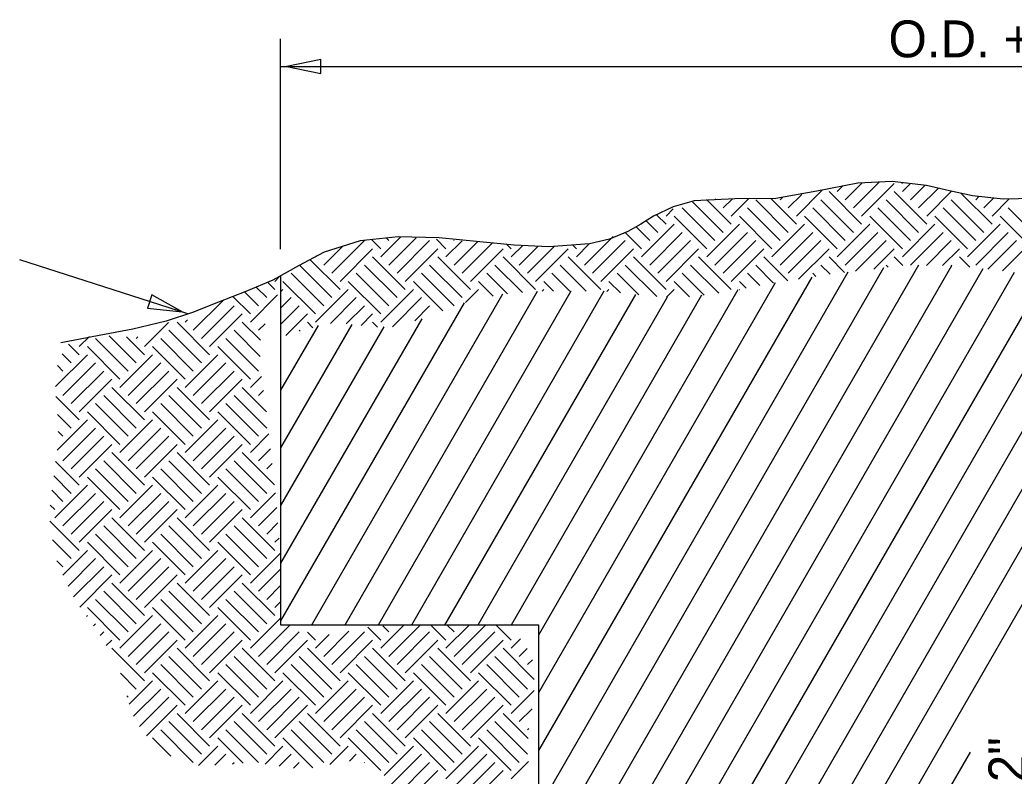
# Model space of a CAD drawing. Extents: x -439.1 to -407.9, y -458.1 to -436.2.
# Drawn here: x -425.749 to -421.705, y -441.707 to -438.633 of the extents above; entities that cross this region are included whole.
import ezdxf

# ---------------------------------------------------------------- set-up
doc = ezdxf.new("R2010")
doc.units = 0
doc.layers.add('Level 4', color=7, linetype='Continuous')
doc.layers.add('Level 45', color=7, linetype='Continuous')

msp = doc.modelspace()

# ---------------------------------------------------------------- linework, layer by layer
at = {"layer": 'Level 4'}
for p, q in [((-424.6882, -439.5658), (-424.6882, -438.7104)), ((-424.6882, -438.8229), (-418.4367, -438.8229)), ((-422.3917, -439.3647), (-422.3229, -439.2959)), ((-422.3585, -439.3978), (-422.2537, -439.293)), ((-422.3254, -439.431), (-422.1928, -439.2984)), ((-422.1596, -439.2984), (-422.1628, -439.2952)), ((-422.1596, -439.3315), (-422.1274, -439.2993)), ((-422.5905, -439.431), (-422.484, -439.3244)), ((-422.3254, -439.4641), (-422.4579, -439.3315)), ((-422.4248, -439.3315), (-422.4001, -439.3069)), ((-422.0602, -439.4641), (-422.1928, -439.3315)), ((-422.1265, -439.3647), (-422.068, -439.3062)), ((-422.0933, -439.3978), (-422.013, -439.3175)), ((-422.0602, -439.431), (-421.9592, -439.33)), ((-421.795, -439.4641), (-421.9203, -439.3388)), ((-422.8888, -439.4972), (-423.0138, -439.3723)), ((-422.8557, -439.4641), (-422.9559, -439.3639)), ((-422.922, -439.3647), (-422.9178, -439.3604)), ((-422.8888, -439.3978), (-422.8511, -439.3601)), ((-422.8557, -439.431), (-422.7858, -439.3611)), ((-422.6237, -439.4972), (-422.7562, -439.3647)), ((-422.5905, -439.4641), (-422.695, -439.3596)), ((-422.6568, -439.3647), (-422.6474, -439.3553)), ((-422.6237, -439.3978), (-422.5686, -439.3427)), ((-422.3585, -439.4972), (-422.4911, -439.3647)), ((-422.0933, -439.4972), (-422.2259, -439.3647)), ((-421.8282, -439.4972), (-421.9608, -439.3647)), ((-421.8613, -439.3647), (-421.8481, -439.3515)), ((-421.8282, -439.3978), (-421.7885, -439.3581)), ((-421.795, -439.431), (-421.7259, -439.3618)), ((-423.1209, -439.431), (-423.0912, -439.4013)), ((-422.922, -439.5304), (-423.0546, -439.3978)), ((-422.6568, -439.5304), (-422.7894, -439.3978)), ((-422.3917, -439.5304), (-422.5242, -439.3978)), ((-422.1265, -439.5304), (-422.2591, -439.3978)), ((-421.8613, -439.5304), (-421.9939, -439.3978)), ((-421.5962, -439.5304), (-421.7287, -439.3978)), ((-423.154, -439.4972), (-423.2017, -439.4496)), ((-423.1209, -439.4641), (-423.1584, -439.4265)), ((-422.9551, -439.5635), (-423.0877, -439.431)), ((-422.69, -439.5635), (-422.8225, -439.431)), ((-422.4248, -439.5635), (-422.5574, -439.431)), ((-422.1596, -439.5635), (-422.2922, -439.431)), ((-421.8945, -439.5635), (-422.0271, -439.431)), ((-421.6293, -439.5635), (-421.7619, -439.431)), ((-423.2203, -439.5635), (-423.2865, -439.4974)), ((-423.1871, -439.5304), (-423.2426, -439.4749)), ((-423.2203, -439.5967), (-423.0877, -439.4641)), ((-423.1871, -439.6298), (-423.0546, -439.4972)), ((-422.9551, -439.5967), (-422.8225, -439.4641)), ((-422.922, -439.6298), (-422.7894, -439.4972)), ((-422.69, -439.5967), (-422.5574, -439.4641)), ((-422.6568, -439.6298), (-422.5242, -439.4972)), ((-422.4248, -439.5967), (-422.2922, -439.4641)), ((-422.3917, -439.6298), (-422.2591, -439.4972)), ((-422.1596, -439.5967), (-422.0271, -439.4641)), ((-422.1265, -439.6298), (-421.9939, -439.4972)), ((-421.8945, -439.5967), (-421.7619, -439.4641)), ((-421.8613, -439.6298), (-421.7287, -439.4972)), ((-424.4798, -439.663), (-424.3472, -439.5304)), ((-424.281, -439.5635), (-424.3182, -439.5263)), ((-424.281, -439.5967), (-424.1997, -439.5154)), ((-424.2478, -439.5304), (-424.2583, -439.5199)), ((-424.2478, -439.6298), (-424.1373, -439.5193)), ((-424.2147, -439.663), (-424.0821, -439.5304)), ((-424.0158, -439.5635), (-424.0549, -439.5245)), ((-424.0158, -439.5967), (-423.9501, -439.531)), ((-423.9826, -439.5304), (-423.9842, -439.5289)), ((-423.9826, -439.6298), (-423.8877, -439.5349)), ((-423.9495, -439.663), (-423.8259, -439.5394)), ((-423.4523, -439.6298), (-423.3357, -439.5132)), ((-423.4192, -439.663), (-423.2866, -439.5304)), ((-423.154, -439.663), (-423.0214, -439.5304)), ((-422.8888, -439.663), (-422.7562, -439.5304)), ((-422.6237, -439.663), (-422.4911, -439.5304)), ((-422.3506, -439.655), (-422.2259, -439.5304)), ((-422.0614, -439.631), (-421.9608, -439.5304)), ((-421.812, -439.6468), (-421.6956, -439.5304)), ((-424.513, -439.6298), (-424.4369, -439.5538)), ((-424.4467, -439.6961), (-424.3141, -439.5635)), ((-424.1815, -439.6961), (-424.0489, -439.5635)), ((-423.9164, -439.6961), (-423.7838, -439.5635)), ((-423.7506, -439.5635), (-423.7707, -439.5435)), ((-423.7506, -439.5967), (-423.7025, -439.5485)), ((-423.7175, -439.6298), (-423.6407, -439.5531)), ((-423.6843, -439.663), (-423.576, -439.5547)), ((-423.6512, -439.6961), (-423.5186, -439.5635)), ((-423.4855, -439.5635), (-423.4999, -439.5491)), ((-423.4855, -439.5967), (-423.433, -439.5442)), ((-423.386, -439.6961), (-423.2534, -439.5635)), ((-423.1209, -439.6961), (-422.9883, -439.5635)), ((-422.8557, -439.6961), (-422.7231, -439.5635)), ((-422.5814, -439.687), (-422.4579, -439.5635)), ((-422.2752, -439.646), (-422.1928, -439.5635)), ((-421.9962, -439.6321), (-421.9276, -439.5635)), ((-421.7524, -439.6535), (-421.6624, -439.5635)), ((-425.0651, -439.8279), (-425.7487, -439.6091)), ((-424.4467, -439.7293), (-424.5691, -439.6068)), ((-424.5461, -439.5967), (-424.5424, -439.593)), ((-424.1815, -439.7293), (-424.3141, -439.5967)), ((-423.9164, -439.7293), (-424.0489, -439.5967)), ((-423.6512, -439.7293), (-423.7838, -439.5967)), ((-420.8581, -439.5989), (-423.5795, -444.3124)), ((-423.386, -439.7293), (-423.5186, -439.5967)), ((-423.1209, -439.7293), (-423.2534, -439.5967)), ((-422.8557, -439.7293), (-422.9883, -439.5967)), ((-422.6258, -439.694), (-422.7231, -439.5967)), ((-422.3943, -439.6603), (-422.4579, -439.5967)), ((-422.1576, -439.6319), (-422.1928, -439.5967)), ((-421.8857, -439.6386), (-421.9276, -439.5967)), ((-424.513, -439.7956), (-424.6456, -439.663)), ((-424.4798, -439.7624), (-424.6114, -439.6308)), ((-424.2478, -439.7956), (-424.3804, -439.663)), ((-424.2147, -439.7624), (-424.3472, -439.6298)), ((-423.9826, -439.7956), (-424.1152, -439.663)), ((-423.9495, -439.7624), (-424.0821, -439.6298)), ((-423.7661, -439.747), (-423.8501, -439.663)), ((-423.7046, -439.7421), (-423.8169, -439.6298)), ((-422.0942, -439.6304), (-423.6394, -442.3068)), ((-421.9602, -439.6327), (-423.6394, -442.5412)), ((-422.2358, -439.6413), (-423.6394, -442.0724)), ((-421.8318, -439.6446), (-423.6394, -442.7755)), ((-422.3812, -439.6587), (-423.6394, -441.838)), ((-421.7051, -439.6596), (-423.6394, -443.0099)), ((-423.5125, -439.7354), (-423.5849, -439.663)), ((-423.4462, -439.7354), (-423.5517, -439.6298)), ((-423.2319, -439.7508), (-423.3197, -439.663)), ((-423.1586, -439.7578), (-423.2866, -439.6298)), ((-422.9659, -439.7516), (-423.0546, -439.663)), ((-422.9067, -439.7446), (-423.0214, -439.6298)), ((-422.7396, -439.7128), (-422.7894, -439.663)), ((-422.6831, -439.703), (-422.7562, -439.6298)), ((-422.5113, -439.6759), (-422.5242, -439.663)), ((-422.4535, -439.6674), (-422.4911, -439.6298)), ((-422.2168, -439.639), (-422.2259, -439.6298)), ((-421.9578, -439.6328), (-421.9608, -439.6298)), ((-424.7118, -439.7293), (-424.7407, -439.7005)), ((-424.7118, -439.6961), (-424.6938, -439.678)), ((-424.6884, -439.6753), (-424.6884, -441.0928)), ((-424.5461, -439.8287), (-424.6787, -439.6961)), ((-424.281, -439.8287), (-424.4135, -439.6961)), ((-424.0289, -439.8156), (-424.1484, -439.6961)), ((-423.8232, -439.7561), (-423.8832, -439.6961)), ((-421.5804, -439.6779), (-423.6394, -443.2443)), ((-422.5279, -439.6785), (-423.6394, -441.6037)), ((-421.0426, -439.684), (-423.6394, -444.1818)), ((-421.4551, -439.6953), (-423.6394, -443.4787)), ((-422.6768, -439.702), (-423.6394, -441.3693)), ((-421.3238, -439.7023), (-423.6394, -443.713)), ((-423.5788, -439.7354), (-423.618, -439.6961)), ((-423.3066, -439.7424), (-423.3529, -439.6961)), ((-423.0251, -439.7587), (-423.0877, -439.6961)), ((-422.7948, -439.7238), (-422.8225, -439.6961)), ((-424.7781, -439.7956), (-424.835, -439.7387)), ((-424.745, -439.7624), (-424.7869, -439.7205)), ((-424.6882, -439.7388), (-424.6787, -439.7293)), ((-424.5461, -439.8619), (-424.4135, -439.7293)), ((-423.6444, -439.7374), (-424.4272, -441.0932)), ((-423.5079, -439.7354), (-424.2919, -441.0932)), ((-424.281, -439.8619), (-424.1484, -439.7293)), ((-423.3731, -439.7361), (-424.1566, -441.0932)), ((-423.936, -439.7821), (-423.8832, -439.7293)), ((-421.1918, -439.708), (-423.6394, -443.9474)), ((-422.8286, -439.7306), (-423.6394, -441.1349)), ((-423.6246, -439.7358), (-423.618, -439.7293)), ((-423.3609, -439.7373), (-423.3529, -439.7293)), ((-423.1188, -439.7604), (-423.0877, -439.7293)), ((-422.8227, -439.7294), (-422.8225, -439.7293)), ((-425.0433, -439.895), (-424.9204, -439.772)), ((-424.8113, -439.8287), (-424.8828, -439.7572)), ((-424.8113, -439.8619), (-424.7006, -439.7512)), ((-424.6882, -439.8051), (-424.6456, -439.7624)), ((-423.9416, -439.7834), (-424.6882, -441.0766)), ((-423.7862, -439.7486), (-424.5625, -441.0932)), ((-424.4856, -439.8676), (-424.3804, -439.7624)), ((-424.2337, -439.8809), (-424.1152, -439.7624)), ((-423.2453, -439.7492), (-424.0212, -441.0932)), ((-423.1165, -439.7604), (-423.8859, -441.0932)), ((-422.9768, -439.7529), (-423.7506, -441.0932)), ((-425.0102, -439.9281), (-424.8776, -439.7956)), ((-424.6882, -439.8714), (-424.6124, -439.7956)), ((-424.4211, -439.8694), (-424.3472, -439.7956)), ((-424.1431, -439.8566), (-424.0821, -439.7956)), ((-425.2422, -439.9613), (-425.1441, -439.8632)), ((-424.977, -439.9944), (-425.1096, -439.8619)), ((-425.0764, -439.8619), (-425.0669, -439.8523)), ((-424.977, -439.9613), (-424.8444, -439.8287)), ((-424.7707, -439.9356), (-424.8444, -439.8619)), ((-424.1144, -439.8483), (-424.6882, -440.8422)), ((-424.6666, -439.916), (-424.5793, -439.8287)), ((-424.5566, -439.8845), (-424.5793, -439.8619)), ((-424.3611, -439.8757), (-424.3141, -439.8287)), ((-424.2941, -439.8818), (-424.3141, -439.8619)), ((-425.0102, -440.0276), (-425.1427, -439.895)), ((-424.7712, -440.0014), (-424.8776, -439.895)), ((-424.7781, -439.895), (-424.7515, -439.8684)), ((-424.3986, -439.8717), (-424.6882, -440.3734)), ((-424.5362, -439.8757), (-424.6882, -440.1391)), ((-424.2689, -439.8816), (-424.6882, -440.6078)), ((-424.6092, -439.8982), (-424.6124, -439.895)), ((-425.5073, -439.9613), (-425.4658, -439.9198)), ((-425.3085, -440.0607), (-425.4411, -439.9281)), ((-425.2753, -440.0276), (-425.3851, -439.9178)), ((-425.2422, -439.9944), (-425.315, -439.9216)), ((-425.2753, -439.9281), (-425.2688, -439.9216)), ((-425.0433, -440.0607), (-425.1759, -439.9281)), ((-424.7781, -440.0607), (-424.9107, -439.9281)), ((-425.5073, -439.9944), (-425.5509, -439.9509)), ((-425.3416, -440.0939), (-425.4742, -439.9613)), ((-425.0764, -440.0939), (-425.209, -439.9613)), ((-424.8113, -440.0939), (-424.9439, -439.9613)), ((-425.6038, -440.124), (-425.4742, -439.9944)), ((-425.5405, -440.0276), (-425.5771, -439.991)), ((-425.3416, -440.127), (-425.209, -439.9944)), ((-425.0764, -440.127), (-424.9439, -439.9944)), ((-425.5736, -440.0607), (-425.5959, -440.0384)), ((-425.5736, -440.1602), (-425.4411, -440.0276)), ((-425.5405, -440.1933), (-425.4079, -440.0607)), ((-425.3085, -440.1602), (-425.1759, -440.0276)), ((-425.2753, -440.1933), (-425.1427, -440.0607)), ((-425.0433, -440.1602), (-424.9107, -440.0276)), ((-425.0102, -440.1933), (-424.8776, -440.0607)), ((-425.5073, -440.2265), (-425.3748, -440.0939)), ((-425.2422, -440.2265), (-425.1096, -440.0939)), ((-424.977, -440.2265), (-424.8444, -440.0939)), ((-424.8113, -440.127), (-424.7667, -440.0825)), ((-425.2422, -440.2596), (-425.3748, -440.127)), ((-424.977, -440.2596), (-425.1096, -440.127)), ((-424.7453, -440.2261), (-424.8444, -440.127)), ((-424.7781, -440.1602), (-424.7575, -440.1395)), ((-425.5073, -440.2596), (-425.6022, -440.1647)), ((-425.2753, -440.2927), (-425.4079, -440.1602)), ((-425.0102, -440.2927), (-425.1427, -440.1602)), ((-424.745, -440.2927), (-424.8776, -440.1602)), ((-425.3416, -440.359), (-425.4742, -440.2265)), ((-425.3085, -440.3259), (-425.4411, -440.1933)), ((-425.0764, -440.359), (-425.209, -440.2265)), ((-425.0433, -440.3259), (-425.1759, -440.1933)), ((-424.8113, -440.359), (-424.9439, -440.2265)), ((-424.7781, -440.3259), (-424.9107, -440.1933)), ((-425.5976, -440.383), (-425.4742, -440.2596)), ((-425.5405, -440.2927), (-425.5964, -440.2368)), ((-425.3416, -440.3922), (-425.209, -440.2596)), ((-425.0764, -440.3922), (-424.9439, -440.2596)), ((-425.5736, -440.3259), (-425.5935, -440.306)), ((-425.5736, -440.4253), (-425.4411, -440.2927)), ((-425.3085, -440.4253), (-425.1759, -440.2927)), ((-425.0433, -440.4253), (-424.9107, -440.2927)), ((-425.5405, -440.4585), (-425.4079, -440.3259)), ((-425.2753, -440.4585), (-425.1427, -440.3259)), ((-425.0102, -440.4585), (-424.8776, -440.3259)), ((-424.8113, -440.3922), (-424.7356, -440.3165)), ((-425.5073, -440.4916), (-425.3748, -440.359)), ((-425.2422, -440.4916), (-425.1096, -440.359)), ((-424.977, -440.4916), (-424.8444, -440.359)), ((-424.7781, -440.4253), (-424.7291, -440.3763)), ((-425.5073, -440.5248), (-425.6033, -440.4288)), ((-425.2753, -440.5579), (-425.4079, -440.4253)), ((-425.2422, -440.5248), (-425.3748, -440.3922)), ((-425.0102, -440.5579), (-425.1427, -440.4253)), ((-424.977, -440.5248), (-425.1096, -440.3922)), ((-424.745, -440.5579), (-424.8776, -440.4253)), ((-424.7132, -440.5234), (-424.8444, -440.3922)), ((-425.3085, -440.5911), (-425.4411, -440.4585)), ((-425.0433, -440.5911), (-425.1759, -440.4585)), ((-424.7781, -440.5911), (-424.9107, -440.4585)), ((-424.745, -440.4585), (-424.7226, -440.4361)), ((-425.5405, -440.5579), (-425.6112, -440.4872)), ((-425.3416, -440.6242), (-425.4742, -440.4916)), ((-425.0764, -440.6242), (-425.209, -440.4916)), ((-424.8113, -440.6242), (-424.9439, -440.4916)), ((-425.5736, -440.5911), (-425.6192, -440.5455)), ((-425.6068, -440.6573), (-425.4742, -440.5248)), ((-425.3416, -440.6573), (-425.209, -440.5248)), ((-425.0764, -440.6573), (-424.9439, -440.5248)), ((-425.5736, -440.6905), (-425.4411, -440.5579)), ((-425.5405, -440.7236), (-425.4079, -440.5911)), ((-425.3085, -440.6905), (-425.1759, -440.5579)), ((-425.2753, -440.7236), (-425.1427, -440.5911)), ((-425.0433, -440.6905), (-424.9107, -440.5579)), ((-425.0102, -440.7236), (-424.8776, -440.5911)), ((-424.8113, -440.6573), (-424.7097, -440.5557)), ((-425.6068, -440.6242), (-425.6254, -440.6056)), ((-425.5073, -440.7568), (-425.3748, -440.6242)), ((-425.2422, -440.7568), (-425.1096, -440.6242)), ((-424.977, -440.7568), (-424.8444, -440.6242)), ((-424.7781, -440.6905), (-424.7035, -440.6158)), ((-425.5073, -440.7899), (-425.6267, -440.6706)), ((-425.2422, -440.7899), (-425.3748, -440.6573)), ((-424.977, -440.7899), (-425.1096, -440.6573)), ((-424.7118, -440.7899), (-424.8444, -440.6573)), ((-425.2753, -440.8231), (-425.4079, -440.6905)), ((-425.0102, -440.8231), (-425.1427, -440.6905)), ((-424.745, -440.8231), (-424.8776, -440.6905)), ((-424.745, -440.7236), (-424.6991, -440.6778)), ((-425.5405, -440.8231), (-425.6162, -440.7474)), ((-425.3085, -440.8562), (-425.4411, -440.7236)), ((-425.0433, -440.8562), (-425.1759, -440.7236)), ((-424.7781, -440.8562), (-424.9107, -440.7236)), ((-424.7118, -440.7568), (-424.6947, -440.7397)), ((-425.5746, -440.8903), (-425.4742, -440.7899)), ((-425.3416, -440.8894), (-425.4742, -440.7568)), ((-425.3416, -440.9225), (-425.209, -440.7899)), ((-425.0764, -440.8894), (-425.209, -440.7568)), ((-425.0764, -440.9225), (-424.9439, -440.7899)), ((-424.8113, -440.8894), (-424.9439, -440.7568)), ((-425.5736, -440.8562), (-425.5982, -440.8316)), ((-425.5528, -440.9348), (-425.4411, -440.8231)), ((-425.3085, -440.9557), (-425.1759, -440.8231)), ((-425.0433, -440.9557), (-424.9107, -440.8231)), ((-424.8113, -440.9225), (-424.6908, -440.802)), ((-425.531, -440.9793), (-425.4079, -440.8562)), ((-425.2753, -440.9888), (-425.1427, -440.8562)), ((-425.0102, -440.9888), (-424.8776, -440.8562)), ((-424.7781, -440.9557), (-424.6902, -440.8677)), ((-425.5054, -441.02), (-425.3748, -440.8894)), ((-425.2422, -441.0219), (-425.1096, -440.8894)), ((-424.977, -441.0219), (-424.8444, -440.8894)), ((-425.2753, -441.0882), (-425.4079, -440.9557)), ((-425.2422, -441.0551), (-425.3748, -440.9225)), ((-425.0102, -441.0882), (-425.1427, -440.9557)), ((-424.977, -441.0551), (-425.1096, -440.9225)), ((-424.745, -441.0882), (-424.8776, -440.9557)), ((-424.7118, -441.0551), (-424.8444, -440.9225)), ((-424.745, -440.9888), (-424.6896, -440.9334)), ((-425.3085, -441.1214), (-425.4411, -440.9888)), ((-425.0433, -441.1214), (-425.1759, -440.9888)), ((-424.7781, -441.1214), (-424.9107, -440.9888)), ((-425.3416, -441.1545), (-425.4742, -441.0219)), ((-425.0764, -441.1545), (-425.209, -441.0219)), ((-424.8113, -441.1545), (-424.9439, -441.0219)), ((-424.7118, -441.0219), (-424.6891, -440.9992)), ((-425.4779, -441.0588), (-425.4742, -441.0551)), ((-425.3416, -441.1877), (-425.209, -441.0551)), ((-425.0764, -441.1877), (-424.9439, -441.0551)), ((-424.8113, -441.1877), (-424.6885, -441.0649)), ((-425.4498, -441.0969), (-425.4411, -441.0882)), ((-425.3085, -441.2208), (-425.1759, -441.0882)), ((-425.0433, -441.2208), (-424.9107, -441.0882)), ((-424.7781, -441.2208), (-424.6505, -441.0932)), ((-424.6884, -441.0928), (-423.6397, -441.0928)), ((-424.513, -441.2208), (-424.4105, -441.1184)), ((-424.281, -441.1545), (-424.3333, -441.1022)), ((-424.281, -441.1877), (-424.1865, -441.0932)), ((-424.2478, -441.1214), (-424.2723, -441.0969)), ((-424.2478, -441.2208), (-424.1202, -441.0932)), ((-424.0158, -441.1545), (-424.0771, -441.0932)), ((-424.0158, -441.1877), (-423.9213, -441.0932)), ((-423.9826, -441.1214), (-424.0108, -441.0932)), ((-423.9826, -441.2208), (-423.855, -441.0932)), ((-423.7506, -441.1545), (-423.812, -441.0932)), ((-423.6397, -441.0928), (-423.6397, -445.029)), ((-425.422, -441.1355), (-425.4079, -441.1214)), ((-425.3972, -441.177), (-425.3748, -441.1545)), ((-425.2753, -441.254), (-425.1427, -441.1214)), ((-425.2422, -441.2871), (-425.1096, -441.1545)), ((-425.0102, -441.254), (-424.8776, -441.1214)), ((-424.977, -441.2871), (-424.8444, -441.1545)), ((-424.745, -441.254), (-424.6124, -441.1214)), ((-424.7118, -441.2871), (-424.5793, -441.1545)), ((-424.5461, -441.1545), (-424.5786, -441.1221)), ((-424.5461, -441.1877), (-424.4902, -441.1317)), ((-424.4798, -441.254), (-424.3472, -441.1214)), ((-424.4467, -441.2871), (-424.3141, -441.1545)), ((-424.2147, -441.254), (-424.0821, -441.1214)), ((-424.1815, -441.2871), (-424.0489, -441.1545)), ((-423.9495, -441.254), (-423.8169, -441.1214)), ((-423.9164, -441.2871), (-423.7838, -441.1545)), ((-423.7506, -441.1877), (-423.7123, -441.1494)), ((-425.2422, -441.3203), (-425.3748, -441.1877)), ((-424.977, -441.3203), (-425.1096, -441.1877)), ((-424.7118, -441.3203), (-424.8444, -441.1877)), ((-424.4467, -441.3203), (-424.5793, -441.1877)), ((-424.1815, -441.3203), (-424.3141, -441.1877)), ((-423.9164, -441.3203), (-424.0489, -441.1877)), ((-423.6573, -441.3142), (-423.7838, -441.1877)), ((-423.7175, -441.2208), (-423.6852, -441.1885)), ((-425.0102, -441.3534), (-425.1427, -441.2208)), ((-424.745, -441.3534), (-424.8776, -441.2208)), ((-424.4798, -441.3534), (-424.6124, -441.2208)), ((-424.2147, -441.3534), (-424.3472, -441.2208)), ((-423.9495, -441.3534), (-424.0821, -441.2208)), ((-423.6843, -441.3534), (-423.8169, -441.2208)), ((-423.6843, -441.254), (-423.6645, -441.2341)), ((-425.0433, -441.3866), (-425.1759, -441.254)), ((-424.7781, -441.3866), (-424.9107, -441.254)), ((-424.513, -441.3866), (-424.6456, -441.254)), ((-424.2478, -441.3866), (-424.3804, -441.254)), ((-423.9826, -441.3866), (-424.1152, -441.254)), ((-423.7175, -441.3866), (-423.8501, -441.254)), ((-425.2753, -441.3534), (-425.3401, -441.2887)), ((-425.3041, -441.4153), (-425.209, -441.3203)), ((-425.0764, -441.4197), (-425.209, -441.2871)), ((-425.0764, -441.4528), (-424.9439, -441.3203)), ((-424.8113, -441.4197), (-424.9439, -441.2871)), ((-424.8113, -441.4528), (-424.6787, -441.3203)), ((-424.5461, -441.4197), (-424.6787, -441.2871)), ((-424.5461, -441.4528), (-424.4135, -441.3203)), ((-424.281, -441.4197), (-424.4135, -441.2871)), ((-424.281, -441.4528), (-424.1484, -441.3203)), ((-424.0158, -441.4197), (-424.1484, -441.2871)), ((-424.0158, -441.4528), (-423.8832, -441.3203)), ((-423.7506, -441.4197), (-423.8832, -441.2871)), ((-425.2866, -441.4641), (-425.1759, -441.3534)), ((-425.0433, -441.486), (-424.9107, -441.3534)), ((-424.7781, -441.486), (-424.6456, -441.3534)), ((-424.513, -441.486), (-424.3804, -441.3534)), ((-424.2478, -441.486), (-424.1152, -441.3534)), ((-423.9826, -441.486), (-423.8501, -441.3534)), ((-423.7506, -441.4528), (-423.6571, -441.3593)), ((-425.3085, -441.3866), (-425.3138, -441.3812)), ((-425.2623, -441.5061), (-425.1427, -441.3866)), ((-425.0102, -441.5191), (-424.8776, -441.3866)), ((-424.745, -441.5191), (-424.6124, -441.3866)), ((-424.4798, -441.5191), (-424.3472, -441.3866)), ((-424.2147, -441.5191), (-424.0821, -441.3866)), ((-423.9495, -441.5191), (-423.8169, -441.3866)), ((-425.2336, -441.5437), (-425.1096, -441.4197)), ((-424.977, -441.5523), (-424.8444, -441.4197)), ((-424.7118, -441.5523), (-424.5793, -441.4197)), ((-424.4467, -441.5523), (-424.3141, -441.4197)), ((-424.1815, -441.5523), (-424.0489, -441.4197)), ((-423.9164, -441.5523), (-423.7838, -441.4197)), ((-423.7175, -441.486), (-423.6656, -441.4341)), ((-424.977, -441.5854), (-425.1096, -441.4528)), ((-424.7118, -441.5854), (-424.8444, -441.4528)), ((-424.4467, -441.5854), (-424.5793, -441.4528)), ((-424.1815, -441.5854), (-424.3141, -441.4528)), ((-423.9164, -441.5854), (-424.0489, -441.4528)), ((-423.6815, -441.5552), (-423.7838, -441.4528)), ((-425.0433, -441.6517), (-425.1759, -441.5191)), ((-425.0102, -441.6186), (-425.1427, -441.486)), ((-424.7781, -441.6517), (-424.9107, -441.5191)), ((-424.745, -441.6186), (-424.8776, -441.486)), ((-424.513, -441.6517), (-424.6456, -441.5191)), ((-424.4798, -441.6186), (-424.6124, -441.486)), ((-424.2478, -441.6517), (-424.3804, -441.5191)), ((-424.2147, -441.6186), (-424.3472, -441.486)), ((-423.9826, -441.6517), (-424.1152, -441.5191)), ((-423.9495, -441.6186), (-424.0821, -441.486)), ((-423.7175, -441.6517), (-423.8501, -441.5191)), ((-423.6843, -441.6186), (-423.8169, -441.486)), ((-423.6843, -441.5191), (-423.6791, -441.5139)), ((-425.1343, -441.627), (-425.209, -441.5523)), ((-424.8408, -441.6554), (-424.9439, -441.5523)), ((-424.5578, -441.6732), (-424.6787, -441.5523)), ((-424.281, -441.6849), (-424.4135, -441.5523)), ((-424.0158, -441.6849), (-424.1484, -441.5523)), ((-423.7506, -441.6849), (-423.8832, -441.5523)), ((-425.0224, -441.664), (-424.9439, -441.5854)), ((-424.7518, -441.6585), (-424.6787, -441.5854)), ((-424.4888, -441.6607), (-424.4135, -441.5854)), ((-424.2673, -441.7044), (-424.1484, -441.5854)), ((-424.0158, -441.718), (-423.8832, -441.5854)), ((-424.9554, -441.6632), (-424.9107, -441.6186)), ((-424.6937, -441.6668), (-424.6456, -441.6186)), ((-424.4079, -441.6461), (-424.3804, -441.6186)), ((-424.2448, -441.7481), (-424.1152, -441.6186)), ((-423.9826, -441.7512), (-423.8501, -441.6186)), ((-421.8841, -441.6102), (-422.4935, -442.6658)), ((-424.8837, -441.6578), (-424.8776, -441.6517)), ((-424.6354, -441.6747), (-424.6124, -441.6517)), ((-424.3489, -441.6534), (-424.3472, -441.6517)), ((-424.2147, -441.7843), (-424.0821, -441.6517)), ((-424.1815, -441.8174), (-424.0489, -441.6849)), ((-423.9495, -441.7843), (-423.8169, -441.6517)), ((-423.9164, -441.8174), (-423.7838, -441.6849)), ((-423.7506, -441.718), (-423.6808, -441.6482))]:
    msp.add_line(p, q, dxfattribs=at)
for points in [[(-424.5249, -438.7942), (-424.6632, -438.8229), (-424.5249, -438.8517)], [(-425.2294, -439.8054), (-425.0889, -439.8202), (-425.2119, -439.7507)]]:
    msp.add_lwpolyline(points, close=True, dxfattribs=at)
for points in [[(-421.6248, -439.359), (-421.7498, -439.3624), (-421.874, -439.3486), (-421.9675, -439.328), (-422.0609, -439.307), (-422.2008, -439.2907), (-422.3413, -439.2967), (-422.5075, -439.3297), (-422.6736, -439.359), (-422.8404, -439.36), (-423.0059, -439.3693), (-423.0914, -439.3935), (-423.1721, -439.4316), (-423.2239, -439.4634), (-423.2759, -439.494), (-423.3512, -439.5249), (-423.4314, -439.5441), (-423.5979, -439.5563), (-423.7389, -439.5496), (-423.8782, -439.5355), (-424.0436, -439.5192), (-424.2106, -439.5147), (-424.365, -439.5314), (-424.5117, -439.577), (-424.6157, -439.6333), (-424.7194, -439.6913), (-424.8301, -439.7369), (-424.941, -439.781)], [(-424.941, -439.781), (-425.0462, -439.8229), (-425.1538, -439.8577), (-425.2893, -439.8899), (-425.4263, -439.9162), (-425.5042, -439.931), (-425.5821, -439.9454)]]:
    msp.add_lwpolyline(points, dxfattribs=at)

# ---------------------------------------------------------------- texts
at = {"layer": 'Level 45'}
msp.add_text("O.D. + 3'", height=0.15, dxfattribs=at).set_placement((-422.216, -438.7854))
msp.add_text('12"', height=0.15, rotation=90, dxfattribs=at).set_placement((-421.6593, -441.8439))

doc.saveas('drawing.dxf')
